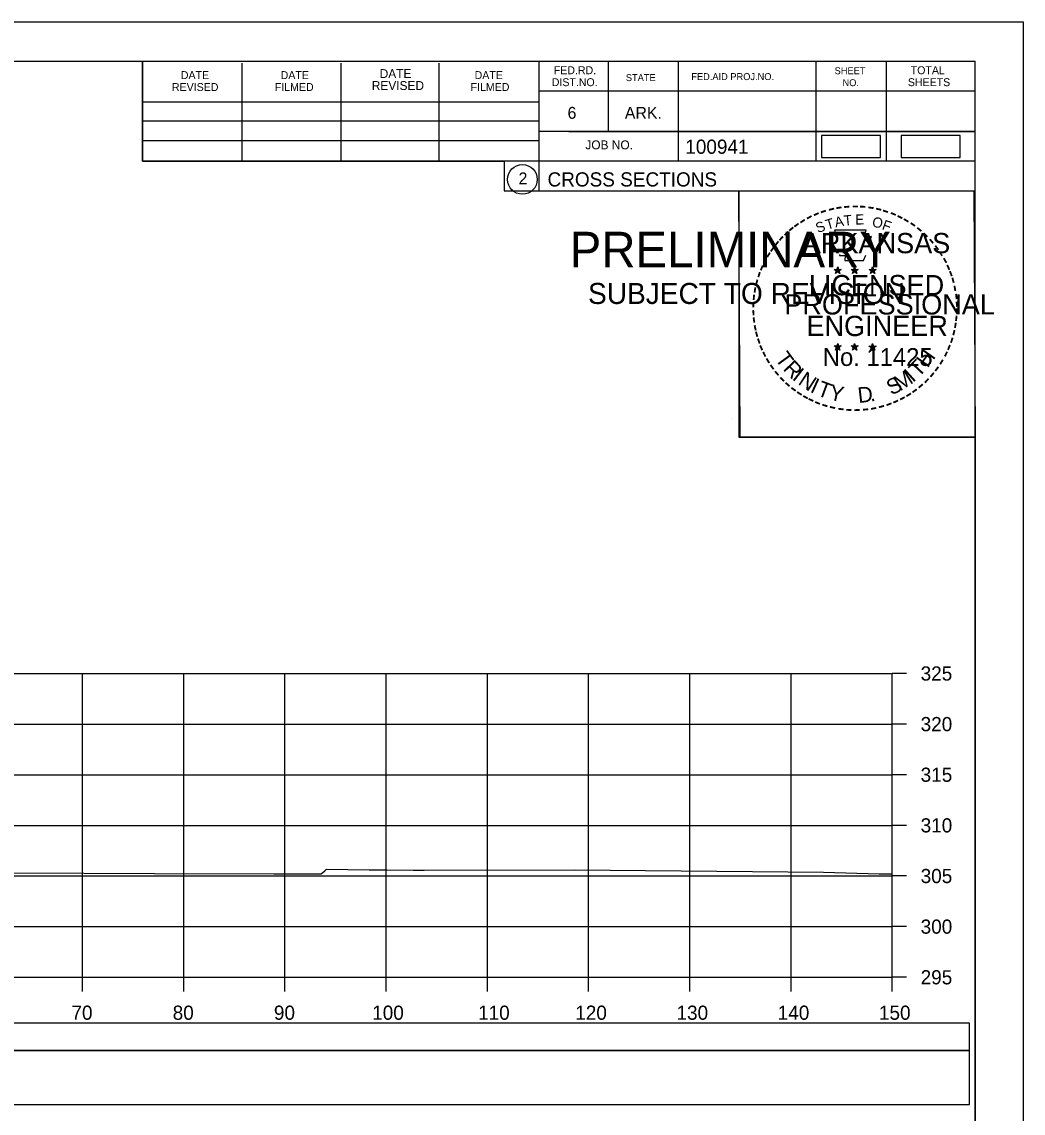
# Model space of a CAD drawing. Extents: x 1370538 to 1372872, y 376220 to 381127.
# Drawn here: x 1370772.6 to 1370871.5, y 378169.8 to 378277.5 of the extents above; entities that cross this region are included whole.
import ezdxf

# ---------------------------------------------------------------- set-up
doc = ezdxf.new("R2010")
doc.units = 0
for name, color, linetype in [('Default', 7, 'Continuous'), ('R_Border Notes', 7, 'Continuous'), ('R_Border PE', 7, 'Continuous'), ('R_Border Prem', 7, 'Continuous'), ('R_Dimension', 7, 'Continuous'), ('R_Grid', 7, 'Continuous'), ('R_Horz Alg Annot', 7, 'Continuous'), ('R_No Plot', 7, 'Continuous'), ('T_Indications', 7, 'Continuous'), ('T_Notes', 7, 'Continuous')]:
    doc.layers.add(name, color=color, linetype=linetype)

msp = doc.modelspace()

# ---------------------------------------------------------------- linework, layer by layer
at = {"layer": 'Default'}
for points in [[(1370851.6, 378264.14), (1370857.43, 378264.14), (1370857.43, 378266.33), (1370851.6, 378266.33)], [(1370859.47, 378264.14), (1370865.3, 378264.14), (1370865.3, 378266.33), (1370859.47, 378266.33)]]:
    msp.add_lwpolyline(points, close=True, dxfattribs=at)
at = {"layer": 'R_Border Notes'}
for p, q in [((1370550.61, 378273.65), (1370866.79, 378273.65)), ((1370784.53, 378263.77), (1370784.53, 378273.65)), ((1370794.39, 378263.77), (1370794.39, 378273.45)), ((1370804.15, 378263.77), (1370804.15, 378273.45)), ((1370813.83, 378263.77), (1370813.83, 378273.45)), ((1370823.69, 378273.65), (1370823.69, 378260.85)), ((1370830.53, 378273.65), (1370830.53, 378266.71)), ((1370837.47, 378273.65), (1370837.47, 378263.77)), ((1370851.05, 378273.65), (1370851.05, 378263.77)), ((1370857.99, 378273.65), (1370857.99, 378263.77)), ((1370866.79, 378068.19), (1370866.79, 378273.65)), ((1370866.79, 378270.71), (1370823.69, 378270.71)), ((1370866.79, 378270.73), (1370866.79, 378270.73)), ((1370784.53, 378269.63), (1370823.69, 378269.63)), ((1370784.53, 378267.77), (1370823.69, 378267.77)), ((1370784.53, 378263.77), (1370784.53, 378265.83)), ((1370784.53, 378265.83), (1370823.69, 378265.83)), ((1370866.79, 378266.71), (1370823.69, 378266.71)), ((1370826.65, 378266.71), (1370866.79, 378266.71)), ((1370866.79, 378263.77), (1370784.53, 378263.77)), ((1370823.69, 378260.85), (1370866.79, 378260.85))]:
    msp.add_line(p, q, dxfattribs=at)
msp.add_circle((1370822.07, 378261.98), 1.47, dxfattribs=at)
at = {"layer": 'R_Border Prem'}
for p, q in [((1370858.61, 378183.19), (1370858.61, 378213.19)), ((1370860.01, 378213.19), (1370858.61, 378213.19)), ((1370860.01, 378208.19), (1370858.61, 378208.19)), ((1370860.01, 378203.19), (1370858.61, 378203.19)), ((1370860.01, 378198.19), (1370858.61, 378198.19)), ((1370860.01, 378193.19), (1370858.61, 378193.19)), ((1370860.01, 378188.19), (1370858.61, 378188.19)), ((1370558.61, 378183.19), (1370858.61, 378183.19)), ((1370778.61, 378181.79), (1370778.61, 378183.19)), ((1370788.61, 378181.79), (1370788.61, 378183.19)), ((1370798.61, 378181.79), (1370798.61, 378183.19)), ((1370808.61, 378181.79), (1370808.61, 378183.19)), ((1370818.61, 378181.79), (1370818.61, 378183.19)), ((1370828.61, 378181.79), (1370828.61, 378183.19)), ((1370838.61, 378181.79), (1370838.61, 378183.19)), ((1370848.61, 378181.79), (1370848.61, 378183.19)), ((1370858.61, 378181.79), (1370858.61, 378183.19)), ((1370860.01, 378183.19), (1370858.61, 378183.19))]:
    msp.add_line(p, q, dxfattribs=at)
at = {"layer": 'R_Dimension'}
msp.add_lwpolyline([(1370771.81, 378193.51), (1370785.72, 378193.44), (1370797.52, 378193.41), (1370802.19, 378193.41), (1370802.55, 378193.7), (1370802.72, 378193.87), (1370806.92, 378193.79), (1370808.68, 378193.79), (1370811.28, 378193.77), (1370812.36, 378193.77), (1370827.23, 378193.8), (1370851.82, 378193.57), (1370857.3, 378193.4), (1370858.61, 378193.39)], dxfattribs=at)
at = {"layer": 'R_Grid'}
for p, q in [((1370558.61, 378213.19), (1370858.61, 378213.19)), ((1370778.61, 378183.19), (1370778.61, 378213.19)), ((1370788.61, 378183.19), (1370788.61, 378213.19)), ((1370798.61, 378183.19), (1370798.61, 378213.19)), ((1370808.61, 378183.19), (1370808.61, 378213.19)), ((1370818.61, 378183.19), (1370818.61, 378213.19)), ((1370828.61, 378183.19), (1370828.61, 378213.19)), ((1370838.61, 378183.19), (1370838.61, 378213.19)), ((1370848.61, 378183.19), (1370848.61, 378213.19)), ((1370858.61, 378183.19), (1370858.61, 378213.19)), ((1370558.61, 378208.19), (1370858.61, 378208.19)), ((1370558.61, 378203.19), (1370858.61, 378203.19)), ((1370558.61, 378198.19), (1370858.61, 378198.19)), ((1370558.61, 378193.19), (1370858.61, 378193.19)), ((1370558.61, 378188.19), (1370858.61, 378188.19)), ((1370558.61, 378183.19), (1370858.61, 378183.19))]:
    msp.add_line(p, q, dxfattribs=at)
at = {"layer": 'R_Horz Alg Annot'}
for points in [[(1370551.13, 378175.95), (1370866.25, 378175.95), (1370866.25, 378178.66), (1370551.13, 378178.66)], [(1370551.13, 378170.63), (1370866.25, 378170.63), (1370866.25, 378175.95), (1370551.13, 378175.95)]]:
    msp.add_lwpolyline(points, close=True, dxfattribs=at)
at = {"layer": 'R_No Plot'}
for p, q in [((1370538.21, 378277.54), (1370871.54, 378277.54)), ((1370842.82, 378238.39), (1370842.82, 378238.39))]:
    msp.add_line(p, q, dxfattribs=at)
for points in [[(1370538.2, 378277.54), (1370871.54, 378277.54), (1370871.54, 378064.2), (1370538.2, 378064.2)], [(1370784.53, 378273.65), (1370784.53, 378263.77), (1370820.26, 378263.77), (1370820.26, 378260.85), (1370843.46, 378260.85), (1370843.46, 378236.52), (1370866.79, 378236.52), (1370866.79, 378068.19), (1370550.61, 378068.19), (1370550.61, 378273.65)], [(1370843.46, 378260.85), (1370866.67, 378260.85), (1370866.79, 378236.52), (1370843.58, 378236.52)]]:
    msp.add_lwpolyline(points, close=True, dxfattribs=at)
at = {"layer": 'T_Indications'}
for p, q in [((1370852.87, 378253.1), (1370853.22, 378252.99)), ((1370852.87, 378253.1), (1370853.12, 378253.06)), ((1370852.87, 378253.1), (1370853.11, 378252.98)), ((1370853, 378252.69), (1370853.22, 378252.99)), ((1370853, 378252.69), (1370853.13, 378252.94)), ((1370853, 378252.69), (1370853.22, 378252.91)), ((1370853.22, 378253.36), (1370853.18, 378253.1)), ((1370853.22, 378252.99), (1370853.22, 378253.36)), ((1370853.22, 378253.36), (1370853.27, 378253.11)), ((1370853.57, 378253.1), (1370853.22, 378252.99)), ((1370853.43, 378252.69), (1370853.22, 378252.99)), ((1370853.43, 378252.69), (1370853.22, 378252.91)), ((1370853.57, 378253.1), (1370853.28, 378253.05)), ((1370853.43, 378252.69), (1370853.3, 378252.99)), ((1370853.57, 378253.1), (1370853.36, 378253)), ((1370854.54, 378253.1), (1370854.89, 378252.99)), ((1370854.54, 378253.1), (1370854.79, 378253.06)), ((1370854.54, 378253.1), (1370854.78, 378252.98)), ((1370854.67, 378252.69), (1370854.89, 378252.99)), ((1370854.67, 378252.69), (1370854.8, 378252.94)), ((1370854.67, 378252.69), (1370854.89, 378252.91)), ((1370854.89, 378253.36), (1370854.85, 378253.1)), ((1370854.89, 378252.99), (1370854.89, 378253.36)), ((1370854.89, 378253.36), (1370854.94, 378253.11)), ((1370855.24, 378253.1), (1370854.89, 378252.99)), ((1370855.1, 378252.69), (1370854.89, 378252.99)), ((1370855.1, 378252.69), (1370854.89, 378252.91)), ((1370855.24, 378253.1), (1370854.95, 378253.05)), ((1370855.1, 378252.69), (1370854.97, 378252.99)), ((1370855.24, 378253.1), (1370855.03, 378253)), ((1370856.31, 378253.09), (1370856.65, 378252.98)), ((1370856.31, 378253.09), (1370856.56, 378253.05)), ((1370856.31, 378253.09), (1370856.54, 378252.97)), ((1370856.44, 378252.68), (1370856.65, 378252.98)), ((1370856.44, 378252.68), (1370856.56, 378252.93)), ((1370856.44, 378252.68), (1370856.65, 378252.9)), ((1370856.65, 378253.34), (1370856.61, 378253.09)), ((1370856.65, 378252.98), (1370856.65, 378253.34)), ((1370856.65, 378253.34), (1370856.7, 378253.09)), ((1370857, 378253.09), (1370856.65, 378252.98)), ((1370856.87, 378252.68), (1370856.65, 378252.98)), ((1370856.87, 378252.68), (1370856.65, 378252.9)), ((1370857, 378253.09), (1370856.72, 378253.04)), ((1370856.87, 378252.68), (1370856.73, 378252.97)), ((1370857, 378253.09), (1370856.8, 378252.99)), ((1370852.87, 378245.53), (1370853.22, 378245.42)), ((1370852.87, 378245.53), (1370853.12, 378245.48)), ((1370852.87, 378245.53), (1370853.1, 378245.41)), ((1370853, 378245.12), (1370853.22, 378245.42)), ((1370853, 378245.12), (1370853.13, 378245.37)), ((1370853, 378245.12), (1370853.21, 378245.34)), ((1370853.22, 378245.78), (1370853.18, 378245.53)), ((1370853.43, 378245.12), (1370853.21, 378245.34)), ((1370853.22, 378245.42), (1370853.22, 378245.78)), ((1370853.22, 378245.78), (1370853.27, 378245.53)), ((1370853.56, 378245.53), (1370853.22, 378245.42)), ((1370853.43, 378245.12), (1370853.22, 378245.42)), ((1370853.56, 378245.53), (1370853.28, 378245.48)), ((1370853.43, 378245.12), (1370853.29, 378245.41)), ((1370853.56, 378245.53), (1370853.36, 378245.43)), ((1370854.54, 378245.53), (1370854.89, 378245.42)), ((1370854.54, 378245.53), (1370854.79, 378245.48)), ((1370854.54, 378245.53), (1370854.77, 378245.41)), ((1370854.67, 378245.12), (1370854.89, 378245.42)), ((1370854.67, 378245.12), (1370854.8, 378245.37)), ((1370854.67, 378245.12), (1370854.88, 378245.34)), ((1370854.89, 378245.78), (1370854.84, 378245.53)), ((1370855.1, 378245.12), (1370854.88, 378245.34)), ((1370854.89, 378245.42), (1370854.89, 378245.78)), ((1370854.89, 378245.78), (1370854.93, 378245.53)), ((1370855.23, 378245.53), (1370854.89, 378245.42)), ((1370855.1, 378245.12), (1370854.89, 378245.42)), ((1370855.23, 378245.53), (1370854.95, 378245.48)), ((1370855.1, 378245.12), (1370854.96, 378245.41)), ((1370855.23, 378245.53), (1370855.03, 378245.43)), ((1370856.3, 378245.52), (1370856.65, 378245.41)), ((1370856.3, 378245.52), (1370856.56, 378245.47)), ((1370856.3, 378245.52), (1370856.54, 378245.4)), ((1370856.44, 378245.11), (1370856.65, 378245.41)), ((1370856.44, 378245.11), (1370856.56, 378245.36)), ((1370856.44, 378245.11), (1370856.65, 378245.33)), ((1370856.65, 378245.77), (1370856.61, 378245.52)), ((1370856.65, 378245.41), (1370856.65, 378245.77)), ((1370856.65, 378245.77), (1370856.7, 378245.52)), ((1370857, 378245.52), (1370856.65, 378245.41)), ((1370856.87, 378245.11), (1370856.65, 378245.41)), ((1370856.87, 378245.11), (1370856.65, 378245.33)), ((1370857, 378245.52), (1370856.71, 378245.47)), ((1370856.87, 378245.11), (1370856.73, 378245.4)), ((1370857, 378245.52), (1370856.8, 378245.42))]:
    msp.add_line(p, q, dxfattribs=at)
for points in [[(1370852.91, 378256.98), (1370853.18, 378256.15)], [(1370856.42, 378256.06), (1370856.57, 378256.34), (1370855.88, 378256.32), (1370856.03, 378256.98), (1370852.91, 378256.98)], [(1370853.4, 378254.56), (1370853.4, 378254.47), (1370853.97, 378254.45), (1370853.91, 378253.98), (1370855.78, 378253.98), (1370855.98, 378254.51)], [(1370853.22, 378253.36), (1370853.43, 378252.69), (1370852.87, 378253.1), (1370853.57, 378253.1), (1370853, 378252.69), (1370853.22, 378253.36)], [(1370854.89, 378253.36), (1370855.1, 378252.69), (1370854.54, 378253.1), (1370855.24, 378253.1), (1370854.67, 378252.69), (1370854.89, 378253.36)], [(1370856.65, 378253.34), (1370856.87, 378252.68), (1370856.31, 378253.09), (1370857, 378253.09), (1370856.44, 378252.68), (1370856.65, 378253.34)], [(1370853.22, 378245.78), (1370853.43, 378245.12), (1370852.87, 378245.53), (1370853.56, 378245.53), (1370853, 378245.12), (1370853.22, 378245.78)], [(1370854.89, 378245.78), (1370855.1, 378245.12), (1370854.54, 378245.53), (1370855.23, 378245.53), (1370854.67, 378245.12), (1370854.89, 378245.78)], [(1370856.65, 378245.77), (1370856.87, 378245.11), (1370856.3, 378245.52), (1370857, 378245.52), (1370856.44, 378245.11), (1370856.65, 378245.77)]]:
    msp.add_lwpolyline(points, dxfattribs=at)
for centre, radius in [((1370853.22, 378252.99), 0.172), ((1370853.22, 378252.99), 0.145), ((1370853.22, 378252.99), 0.116), ((1370853.22, 378252.99), 0.0991), ((1370853.22, 378252.99), 0.0747), ((1370853.22, 378252.99), 0.0495), ((1370853.22, 378252.99), 0.0296), ((1370854.89, 378252.99), 0.172), ((1370854.89, 378252.99), 0.145), ((1370854.89, 378252.99), 0.116), ((1370854.89, 378252.99), 0.0991), ((1370854.89, 378252.99), 0.0747), ((1370854.89, 378252.99), 0.0495), ((1370854.89, 378252.99), 0.0296), ((1370856.65, 378252.98), 0.172), ((1370856.65, 378252.98), 0.145), ((1370856.65, 378252.98), 0.116), ((1370856.65, 378252.98), 0.0991), ((1370856.65, 378252.98), 0.0747), ((1370856.65, 378252.98), 0.0495), ((1370856.65, 378252.98), 0.0296), ((1370853.22, 378245.42), 0.172), ((1370853.22, 378245.42), 0.145), ((1370853.22, 378245.42), 0.116), ((1370853.22, 378245.42), 0.0991), ((1370853.22, 378245.42), 0.0747), ((1370853.22, 378245.42), 0.0495), ((1370853.22, 378245.42), 0.0296), ((1370854.88, 378245.42), 0.172), ((1370854.88, 378245.42), 0.145), ((1370854.88, 378245.42), 0.116), ((1370854.88, 378245.42), 0.0991), ((1370854.88, 378245.42), 0.0747), ((1370854.88, 378245.42), 0.0495), ((1370854.88, 378245.42), 0.0296), ((1370856.65, 378245.41), 0.172), ((1370856.65, 378245.41), 0.145), ((1370856.65, 378245.41), 0.116), ((1370856.65, 378245.41), 0.0991), ((1370856.65, 378245.41), 0.0747), ((1370856.65, 378245.41), 0.0495), ((1370856.65, 378245.41), 0.0296)]:
    msp.add_circle(centre, radius, dxfattribs=at)

# ---------------------------------------------------------------- texts
at = {"layer": 'R_Border Notes'}
for s, height, p in [('DATE', 0.782, (1370788.33, 378271.89)), ('DATE', 0.782, (1370798.19, 378271.89)), ('DATE', 0.879, (1370807.97, 378271.99)), ('DATE', 0.782, (1370817.35, 378271.89)), ('FED.RD.', 0.782, (1370825.17, 378272.37)), ('STATE', 0.684, (1370832.29, 378271.69)), ('FED.AID PROJ.NO.', 0.684, (1370838.75, 378271.79)), ('SHEET', 0.684, (1370852.91, 378272.37)), ('TOTAL', 0.782, (1370860.43, 378272.37)), ('REVISED', 0.782, (1370787.45, 378270.71)), ('FILMED', 0.782, (1370797.61, 378270.71)), ('REVISED', 0.879, (1370807.19, 378270.81)), ('FILMED', 0.782, (1370816.95, 378270.71)), ('DIST.NO.', 0.782, (1370824.97, 378271.19)), ('NO.', 0.684, (1370853.69, 378271.19)), ('SHEETS', 0.782, (1370860.15, 378271.19)), ('6', 1.17, (1370826.53, 378267.97)), ('ARK.', 1.172, (1370832.19, 378267.97)), ('JOB NO.', 0.879, (1370828.29, 378264.95)), ('100941', 1.4, (1370838.16, 378264.51)), ('2', 1.17, (1370821.69, 378261.5)), ('CROSS SECTIONS', 1.4, (1370824.55, 378261.28))]:
    msp.add_text(s, height=height, rotation=360, dxfattribs=at).set_placement(p)
at = {"layer": 'R_Border PE'}
for s, p in [('325', (1370861.41, 378212.49)), ('320', (1370861.41, 378207.49)), ('315', (1370861.41, 378202.49)), ('310', (1370861.41, 378197.49)), ('305', (1370861.41, 378192.49)), ('300', (1370861.41, 378187.49)), ('295', (1370861.41, 378182.49)), ('70', (1370777.52, 378178.99)), ('80', (1370787.52, 378178.99)), ('90', (1370797.52, 378178.99)), ('100', (1370807.23, 378178.99)), ('110', (1370817.69, 378178.99)), ('120', (1370827.29, 378178.99)), ('130', (1370837.29, 378178.99)), ('140', (1370847.29, 378178.99)), ('150', (1370857.29, 378178.99))]:
    msp.add_text(s, height=1.4, dxfattribs=at).set_placement(p)
at = {"layer": 'T_Indications'}
for s, height, rotation, p in [('-', 1.6, 10.2193, (1370853.09, 378258.51)), ('-', 1.6, 5.8968, (1370853.82, 378258.62)), ('-', 1.6, 0.1862, (1370854.59, 378258.69)), ('-', 1.6, 357.743, (1370855.31, 378258.68)), ('-', 1.6, 352.1617, (1370856.06, 378258.62)), ('-', 1.6, 28.7918, (1370850.39, 378257.52)), ('-', 1.6, 24.3072, (1370851.03, 378257.84)), ('-', 1.6, 19.1761, (1370851.66, 378258.11)), ('T', 1, 16.4036, (1370852.18, 378256.99)), ('-', 1.6, 13.6301, (1370852.41, 378258.35)), ('A', 1, 11.2132, (1370853.01, 378257.24)), ('T', 1, 6.0228, (1370853.86, 378257.41)), ('E', 1, 0.8323, (1370854.96, 378257.52)), ('O', 1, 350.4515, (1370856.57, 378257.31)), ('-', 1.6, 347.2049, (1370856.78, 378258.51)), ('-', 1.6, 342.3362, (1370857.41, 378258.35)), ('-', 1.6, 337.8551, (1370858.15, 378258.13)), ('-', 1.6, 334.1211, (1370858.78, 378257.86)), ('-', 1.6, 38.9507, (1370848.74, 378256.38)), ('-', 1.6, 36.2317, (1370849.22, 378256.76)), ('-', 1.6, 34.0636, (1370849.8, 378257.15)), ('S', 1, 21.594, (1370851.27, 378256.66)), ('F', 1, 340.0707, (1370857.52, 378257.08)), ('-', 1.6, 329.6409, (1370859.36, 378257.58)), ('-', 1.6, 325.8627, (1370860, 378257.22)), ('-', 1.6, 320.5297, (1370860.61, 378256.79)), ('-', 1.6, 48.423, (1370847.86, 378255.48)), ('-', 1.6, 42.9622, (1370848.31, 378255.96)), ('ARKANSAS', 2, 360, (1370849.77, 378254.69)), ('-', 1.6, 315.5786, (1370861.21, 378256.3)), ('-', 1.6, 309.8797, (1370861.78, 378255.75)), ('-', 1.6, 54.2325, (1370847.05, 378254.43)), ('-', 1.6, 50.6142, (1370847.46, 378255)), ('-', 1.6, 306.6522, (1370862.3, 378255.15)), ('-', 1.6, 62.8713, (1370846.41, 378253.29)), ('-', 1.6, 58.0706, (1370846.72, 378253.9)), ('-', 1.4, 303.6753, (1370862.79, 378254.58)), ('-', 1.6, 299.6684, (1370863.11, 378253.98)), ('-', 1.6, 72.3945, (1370845.93, 378252.05)), ('-', 1.6, 67.7743, (1370846.15, 378252.68)), ('DWB', 0.01, 360, (1370853.21, 378252.99)), ('DWB', 0.01, 360, (1370854.88, 378252.99)), ('DWB', 0.01, 360, (1370856.64, 378252.98)), ('-', 1.6, 294.6628, (1370863.43, 378253.36)), ('-', 1.6, 290.5728, (1370863.69, 378252.79)), ('-', 1.6, 75.461, (1370845.73, 378251.33)), ('LICENSED', 2, 360, (1370850.36, 378250.54)), ('-', 1.6, 285.1233, (1370863.92, 378252.21)), ('-', 1.6, 81.2013, (1370845.6, 378250.62)), ('PROFESSIONAL', 2, 360, (1370847.94, 378248.64)), ('-', 1.6, 280.5493, (1370864.12, 378251.46)), ('-', 1.6, 276.5962, (1370864.28, 378250.7)), ('-', 1.6, 89.0622, (1370845.5, 378249.23)), ('-', 1.6, 85.1863, (1370845.52, 378249.93)), ('-', 1.6, 274.3301, (1370864.34, 378249.97)), ('-', 1.6, 94.1959, (1370845.53, 378248.5)), ('ENGINEER', 2, 360, (1370850.13, 378246.51)), ('-', 1.6, 263.5172, (1370864.36, 378248.68)), ('-', 1.6, 269.9407, (1370864.38, 378249.34)), ('-', 1.6, 98.9479, (1370845.61, 378247.84)), ('-', 1.6, 101.7149, (1370845.74, 378247.1)), ('-', 1.6, 260.9953, (1370864.29, 378248.02)), ('-', 1.6, 105.4578, (1370845.9, 378246.51)), ('-', 1.6, 252.8681, (1370864, 378246.62)), ('-', 1.6, 255.7626, (1370864.18, 378247.34)), ('-', 1.6, 109.0874, (1370846.12, 378245.88)), ('-', 1.6, 114.0643, (1370846.37, 378245.28)), ('No. 11425', 1.757, 360, (1370851.75, 378243.56)), ('DWB', 0.01, 360, (1370853.2, 378245.41)), ('DWB', 0.01, 360, (1370854.87, 378245.41)), ('DWB', 0.01, 360, (1370856.64, 378245.4)), ('H', 1.54, 54.6088, (1370862.1, 378243.29)), ('-', 1.6, 247.8887, (1370863.77, 378245.95)), ('-', 1.6, 115.7289, (1370846.68, 378244.66)), ('-', 1.6, 120.4471, (1370847.03, 378244.08)), ('T', 1.54, 306.0406, (1370846.98, 378244.26)), ('T', 1.54, 46.6444, (1370861.21, 378242.35)), ('-', 1.6, 239.0712, (1370863.12, 378244.57)), ('-', 1.6, 244.6197, (1370863.51, 378245.32)), ('-', 1.6, 125.8934, (1370847.44, 378243.52)), ('-', 1.6, 130.7181, (1370847.9, 378242.97)), ('R', 1.54, 314.005, (1370847.74, 378243.21)), ('I', 1.54, 321.9694, (1370848.64, 378242.28)), ('M', 1.54, 32.6563, (1370859.36, 378241.02)), ('I', 1.54, 42.1136, (1370860.64, 378241.87)), ('-', 1.6, 233.8452, (1370862.72, 378243.92)), ('-', 1.6, 134.2238, (1370848.42, 378242.42)), ('N', 1.54, 326.5002, (1370849.21, 378241.81)), ('I', 1.54, 335.3603, (1370850.41, 378241.02)), ('T', 1.54, 339.8912, (1370851.08, 378240.69)), ('S', 1.54, 26.9312, (1370858.52, 378240.62)), ('-', 1.6, 225.7653, (1370861.81, 378242.79)), ('-', 1.6, 231.2538, (1370862.29, 378243.35)), ('-', 1.6, 138.9338, (1370848.94, 378241.96)), ('-', 1.6, 144.6463, (1370849.5, 378241.55)), ('-', 1.6, 148.0898, (1370850.06, 378241.18)), ('Y', 1.54, 347.8556, (1370852.29, 378240.25)), ('D', 1.54, 6.3969, (1370855.28, 378239.89)), ('-', 1.6, 215.7363, (1370860.74, 378241.81)), ('-', 1.6, 221.0851, (1370861.28, 378242.28)), ('-', 1.6, 151.5704, (1370850.64, 378240.85)), ('-', 1.6, 154.6002, (1370851.16, 378240.61)), ('-', 1.6, 158.5612, (1370851.78, 378240.35)), ('.', 1.54, 13.7642, (1370856.47, 378240.02)), ('-', 1.6, 200.7184, (1370858.4, 378240.48)), ('-', 1.6, 204.2516, (1370859.02, 378240.75)), ('-', 1.6, 207.3568, (1370859.64, 378241.07)), ('-', 1.6, 212.2491, (1370860.2, 378241.42)), ('-', 1.6, 162.7983, (1370852.47, 378240.14)), ('-', 1.6, 167.5555, (1370853.19, 378239.98)), ('-', 1.6, 173.1155, (1370853.96, 378239.87)), ('-', 1.6, 176.5183, (1370854.71, 378239.81)), ('-', 1.6, 181.5918, (1370855.45, 378239.83)), ('-', 1.6, 185.8167, (1370856.26, 378239.91)), ('-', 1.6, 191.2858, (1370856.99, 378240.04)), ('-', 1.6, 195.4743, (1370857.72, 378240.24))]:
    msp.add_text(s, height=height, rotation=rotation, dxfattribs=at).set_placement(p)
at = {"layer": 'T_Notes'}
for s, height, p in [('PRELIMINARY', 3.5, (1370826.74, 378253.31)), ('DWB', 0.01, (1370827.48, 378255.16)), ('SUBJECT TO REVISION', 2.0751, (1370828.55, 378249.68))]:
    msp.add_text(s, height=height, rotation=360, dxfattribs=at).set_placement(p)

doc.saveas('drawing.dxf')
